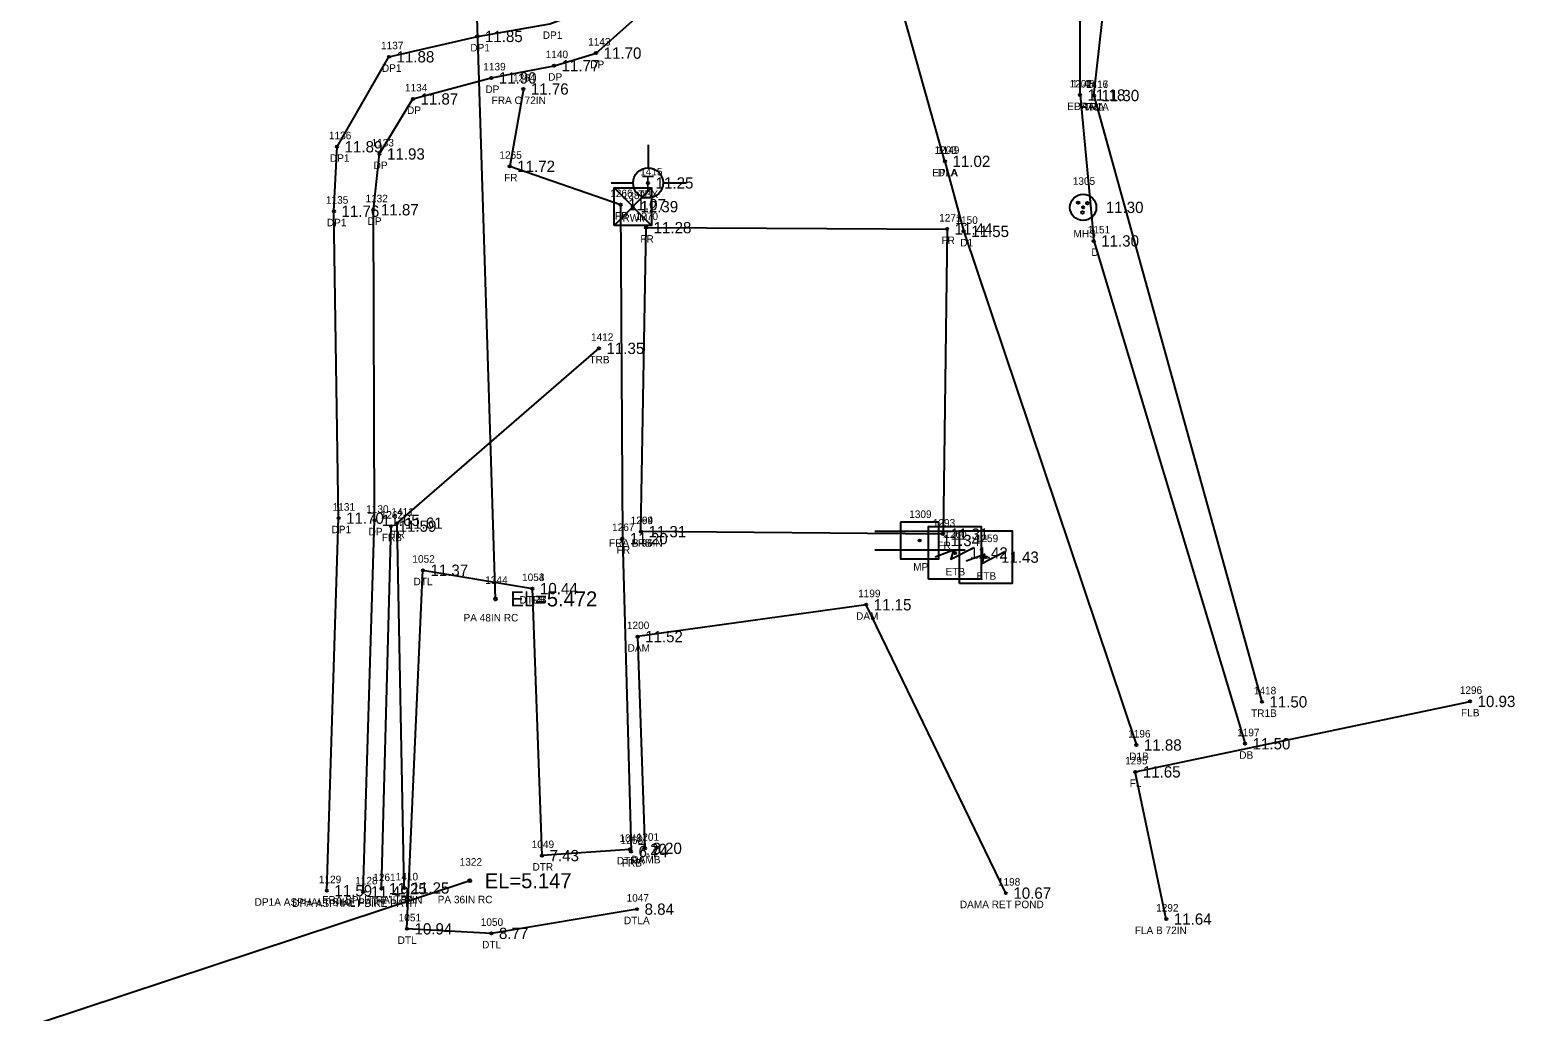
# Model space of a CAD drawing. Extents: x 2072307 to 2072993, y 127574 to 129736.
# Drawn here: x 2072650 to 2072850.3, y 128223.8 to 128354.3 of the extents above; entities that cross this region are included whole.
import ezdxf

# ---------------------------------------------------------------- set-up
doc = ezdxf.new("R2010")
doc.units = 0
for name, color, linetype in [('RD_EX_Dam', 7, 'Continuous'), ('RD_EX_Dam_txCode', 7, 'Continuous'), ('RD_EX_DR_Inlet', 7, 'Continuous'), ('RD_EX_DR_Pipe', 7, 'Continuous'), ('RD_EX_DR_Pipe_txCode', 7, 'Continuous'), ('RD_EX_Driveway', 7, 'Continuous'), ('RD_EX_Driveway_txCode', 7, 'Continuous'), ('RD_EX_Fence_Other', 7, 'Continuous'), ('RD_EX_Fence_Other_txCode', 7, 'Continuous'), ('RD_EX_H2O', 7, 'Continuous'), ('RD_EX_H2O_txCode', 7, 'Continuous'), ('RD_EX_Road', 7, 'Continuous'), ('RD_EX_Road_txCode', 7, 'Continuous'), ('RD_EX_RW', 7, 'Continuous'), ('RD_EX_RW_TxCode', 7, 'Continuous'), ('RD_EX_TX_Dam_ELEV', 7, 'Continuous'), ('RD_EX_TX_Driveway_ELEV', 7, 'Continuous'), ('RD_EX_TX_Fence_Other_ELEV', 7, 'Continuous'), ('RD_EX_TX_H2O_ELEV', 7, 'Continuous'), ('RD_EX_TX_Road_ELEV', 7, 'Continuous'), ('RD_EX_TX_RW_ELEV', 7, 'Continuous'), ('RD_EX_TX_UT_ELEV', 7, 'Continuous'), ('RD_EX_TX_VEG_ELEV', 7, 'Continuous'), ('RD_EX_UT', 7, 'Continuous'), ('RD_EX_UT_txCode', 7, 'Continuous'), ('RD_EX_VEG', 7, 'Continuous'), ('RD_EX_VEG_txCode', 7, 'Continuous'), ('RD_SMD_Locator', 7, 'Continuous'), ('RD_TX_Pipe_ElevEX', 7, 'Continuous')]:
    doc.layers.add(name, color=color, linetype=linetype)

msp = doc.modelspace()

# ---------------------------------------------------------------- linework, layer by layer
at = {"layer": 'RD_EX_Dam'}
msp.add_lwpolyline([(2072779.59, 128239.58), (2072761.03, 128277.92), (2072730.66, 128273.68), (2072731.64, 128245.54)], dxfattribs=at)
at = {"layer": 'RD_EX_DR_Inlet'}
for centre, radius in [((2072789.86, 128330.75), 1.75), ((2072789.2, 128331.38), 0.175), ((2072789.78, 128330.09), 0.175), ((2072790.42, 128331.31), 0.175)]:
    msp.add_circle(centre, radius, dxfattribs=at)
at = {"layer": 'RD_EX_DR_Pipe'}
for p, q in [((2072711.77, 128278.7), (2072708.75, 128375.17)), ((2072708.36, 128241.23), (2072389.02, 128135.57))]:
    msp.add_line(p, q, dxfattribs=at)
at = {"layer": 'RD_EX_Driveway'}
for points in [[(2072689.37, 128239.9), (2072690.93, 128289.43), (2072690.32, 128330.24), (2072690.73, 128338.81), (2072697.63, 128350.77), (2072709.38, 128353.48), (2072719, 128355.15), (2072723.52, 128356.83), (2072727.18, 128360.82), (2072729.07, 128366.04), (2072736.87, 128415.65), (2072743.44, 128446.63), (2072749.73, 128459.37), (2072755.76, 128468.63), (2072761.76, 128476.56), (2072776.61, 128495.01), (2072792.09, 128518.96), (2072805.19, 128542.59), (2072810.66, 128554.44), (2072797.46, 128551.01)], [(2072694.21, 128239.74), (2072695.7, 128289.15), (2072695.56, 128330.43), (2072696.37, 128337.85), (2072700.81, 128345.17), (2072711.22, 128347.96), (2072719.56, 128349.59), (2072725.15, 128351.26), (2072733.07, 128358.33), (2072734.19, 128365.42), (2072741.79, 128414.16), (2072748.82, 128445.27), (2072754.15, 128456.57), (2072759.92, 128465.41), (2072766.21, 128473.75), (2072780.47, 128491.8), (2072796.27, 128516), (2072809.9, 128540.1), (2072821.01, 128555.78)], [(2072789.45, 128345.69), (2072791.26, 128326.29), (2072811.38, 128259.44)], [(2072771.5, 128336.87), (2072773.99, 128327.56), (2072796.93, 128259.27)]]:
    msp.add_lwpolyline(points, dxfattribs=at)
at = {"layer": 'RD_EX_Fence_Other'}
msp.add_line((2072696.63, 128240.18), (2072697.91, 128288.37), dxfattribs=at)
for points in [[(2072715.48, 128346.49), (2072713.67, 128336.21), (2072728.41, 128331.12), (2072728.64, 128286.72), (2072729.79, 128245.11)], [(2072731.1, 128287.64), (2072731.79, 128328.06), (2072771.79, 128327.87), (2072771.24, 128287.31), (2072731.1, 128287.64)], [(2072800.91, 128236.13), (2072796.79, 128255.7), (2072841.27, 128265.07)]]:
    msp.add_lwpolyline(points, dxfattribs=at)
at = {"layer": 'RD_EX_H2O'}
for points in [[(2072730.59, 128237.45), (2072711.24, 128234.23), (2072700.02, 128234.83), (2072702.13, 128282.51), (2072716.69, 128280.07)], [(2072729.65, 128245.4), (2072717.97, 128244.57), (2072716.69, 128280.07)]]:
    msp.add_lwpolyline(points, dxfattribs=at)
at = {"layer": 'RD_EX_Road'}
for points in [[(2072789.45, 128345.69), (2072789.46, 128382.93), (2072788.01, 128408.09), (2072794.06, 128431.26), (2072804.3, 128453.88), (2072840.7, 128525.64), (2072876.68, 128596.08), (2072888.72, 128617.36), (2072893.24, 128622.62), (2072899.84, 128627.36), (2072910.72, 128631.76), (2072918.79, 128632.23), (2072935.82, 128627.02), (2072957.37, 128619.98)], [(2072771.5, 128336.87), (2072760.1, 128377.44)]]:
    msp.add_lwpolyline(points, dxfattribs=at)
at = {"layer": 'RD_EX_RW'}
for p, q in [((2072727.53, 128328.35), (2072732.53, 128333.35)), ((2072732.53, 128328.35), (2072727.53, 128333.35)), ((2072732.53, 128333.35), (2072732.53, 128328.35))]:
    msp.add_line(p, q, dxfattribs=at)
msp.add_lwpolyline([(2072727.53, 128328.35), (2072727.53, 128333.35), (2072732.53, 128333.35), (2072732.53, 128328.35)], close=True, dxfattribs=at)
at = {"layer": 'RD_EX_UT'}
for p, q in [((2072732.06, 128339.07), (2072732.06, 128336)), ((2072727.13, 128334.01), (2072730.06, 128334.01)), ((2072734.06, 128334.01), (2072737.13, 128334.01)), ((2072762.2, 128287.71), (2072774.2, 128287.71)), ((2072762.2, 128285.21), (2072774.2, 128285.21))]:
    msp.add_line(p, q, dxfattribs=at)
for points in [[(2072765.64, 128288.96), (2072770.64, 128288.96), (2072770.64, 128283.96), (2072765.64, 128283.96)], [(2072769.32, 128281.31), (2072769.32, 128288.31), (2072776.32, 128288.31), (2072776.32, 128281.31)], [(2072773.45, 128280.75), (2072773.45, 128287.75), (2072780.45, 128287.75), (2072780.45, 128280.75)]]:
    msp.add_lwpolyline(points, close=True, dxfattribs=at)
for points in [[(2072770.22, 128284.31), (2072772.64, 128285.21), (2072772.29, 128283.96), (2072775.34, 128285.55)], [(2072774.34, 128283.74), (2072776.77, 128284.64), (2072776.42, 128283.39), (2072779.47, 128284.99)]]:
    msp.add_lwpolyline(points, dxfattribs=at)
msp.add_circle((2072732.06, 128334), 2, dxfattribs=at)
at = {"layer": 'RD_EX_VEG'}
msp.add_line((2072791.29, 128345.62), (2072813.61, 128265.01), dxfattribs=at)
for points in [[(2072791.29, 128345.62), (2072800.72, 128429.53), (2072808.9, 128452.58), (2072870.32, 128568.64), (2072876.57, 128573.6), (2072916.77, 128564.68), (2072920.97, 128548.67)], [(2072699.63, 128240.27), (2072698.73, 128288.77), (2072725.53, 128312.01)]]:
    msp.add_lwpolyline(points, dxfattribs=at)
at = {"layer": 'RD_SMD_Locator'}
for centre, radius in [((2072709.38, 128353.48), 0.15), ((2072697.63, 128350.77), 0.15), ((2072719.56, 128349.59), 0.15), ((2072725.15, 128351.26), 0.15), ((2072711.22, 128347.96), 0.15), ((2072715.48, 128346.49), 0.15), ((2072789.45, 128345.69), 0.15), ((2072789.45, 128345.69), 0.15), ((2072791.29, 128345.62), 0.15), ((2072791.29, 128345.62), 0.15), ((2072700.81, 128345.17), 0.15), ((2072690.73, 128338.81), 0.15), ((2072696.37, 128337.85), 0.15), ((2072713.67, 128336.21), 0.15), ((2072771.5, 128336.87), 0.15), ((2072771.5, 128336.87), 0.15), ((2072732.06, 128334), 0.15), ((2072690.32, 128330.24), 0.15), ((2072695.56, 128330.43), 0.15), ((2072728.41, 128331.12), 0.15), ((2072730.03, 128330.85), 0.15), ((2072789.86, 128330.75), 0.15), ((2072731.79, 128328.06), 0.15), ((2072771.79, 128327.87), 0.15), ((2072773.99, 128327.56), 0.15), ((2072791.26, 128326.29), 0.15), ((2072725.53, 128312.01), 0.15), ((2072690.93, 128289.43), 0.15), ((2072695.7, 128289.15), 0.15), ((2072697.91, 128288.37), 0.15), ((2072698.73, 128288.77), 0.15), ((2072731.1, 128287.64), 0.15), ((2072731.1, 128287.64), 0.15), ((2072728.64, 128286.72), 0.15), ((2072768.14, 128286.46), 0.15), ((2072771.24, 128287.31), 0.15), ((2072772.82, 128284.81), 0.15), ((2072776.95, 128284.25), 0.15), ((2072702.13, 128282.51), 0.15), ((2072716.69, 128280.07), 0.15), ((2072716.69, 128280.07), 0.15), ((2072711.77, 128278.7), 0.2), ((2072761.03, 128277.92), 0.15), ((2072730.66, 128273.68), 0.15), ((2072813.61, 128265.01), 0.15), ((2072841.27, 128265.07), 0.15), ((2072811.38, 128259.44), 0.15), ((2072796.93, 128259.27), 0.15), ((2072796.79, 128255.7), 0.15), ((2072729.65, 128245.4), 0.15), ((2072731.64, 128245.54), 0.15), ((2072717.97, 128244.57), 0.15), ((2072729.79, 128245.11), 0.15), ((2072689.37, 128239.9), 0.15), ((2072694.21, 128239.74), 0.15), ((2072696.63, 128240.18), 0.15), ((2072699.63, 128240.27), 0.15), ((2072708.36, 128241.23), 0.2), ((2072779.59, 128239.58), 0.15), ((2072730.59, 128237.45), 0.15), ((2072800.91, 128236.13), 0.15), ((2072700.02, 128234.83), 0.15), ((2072711.24, 128234.23), 0.15)]:
    msp.add_circle(centre, radius, dxfattribs=at)

# ---------------------------------------------------------------- texts
at = {"layer": 'RD_EX_Dam_txCode'}
for s, p in [('1199', (2072759.96, 128278.92)), ('1200', (2072729.24, 128274.68)), ('DAM', (2072759.69, 128275.92)), ('DAM', (2072729.33, 128271.68)), ('1201', (2072730.54, 128246.54)), ('DAMB', (2072729.84, 128243.54)), ('1198', (2072778.53, 128240.58)), ('DAMA RET POND', (2072773.48, 128237.58))]:
    msp.add_text(s, height=1, dxfattribs=at).set_placement(p)
at = {"layer": 'RD_EX_DR_Pipe_txCode'}
for s, p in [('1344', (2072710.42, 128280.7)), ('PA 48IN RC', (2072707.53, 128275.7)), ('1322', (2072707.02, 128243.23)), ('PA 36IN RC', (2072704.1, 128238.23))]:
    msp.add_text(s, height=1, dxfattribs=at).set_placement(p)
at = {"layer": 'RD_EX_Driveway_txCode'}
for s, p in [('DP1', (2072718.06, 128353.15)), ('1137', (2072696.57, 128351.77)), ('DP1', (2072708.44, 128351.48)), ('1143', (2072724.09, 128352.26)), ('DP1', (2072696.69, 128348.77)), ('1139', (2072710.16, 128348.96)), ('1140', (2072718.45, 128350.59)), ('DP', (2072724.37, 128349.26)), ('DP', (2072718.78, 128347.59)), ('1148', (2072788.38, 128346.69)), ('1134', (2072699.75, 128346.17)), ('DP', (2072710.44, 128345.96)), ('DP', (2072700.03, 128343.17)), ('DA', (2072788.65, 128343.69)), ('1136', (2072689.65, 128339.81)), ('1133', (2072695.31, 128338.85)), ('DP1', (2072689.79, 128336.81)), ('1149', (2072770.44, 128337.87)), ('DP', (2072695.59, 128335.85)), ('D1A', (2072770.54, 128334.87)), ('1135', (2072689.25, 128331.24)), ('1132', (2072694.5, 128331.43)), ('DP1', (2072689.37, 128328.24)), ('DP', (2072694.78, 128328.43)), ('1150', (2072772.89, 128328.56)), ('1151', (2072790.48, 128327.29)), ('D1', (2072773.52, 128325.56)), ('D', (2072790.95, 128324.29)), ('1131', (2072690.15, 128290.43)), ('1130', (2072694.6, 128290.15)), ('DP1', (2072689.99, 128287.43)), ('DP', (2072694.92, 128287.15)), ('1196', (2072795.84, 128260.27)), ('1197', (2072810.32, 128260.44)), ('D1B', (2072795.98, 128257.27)), ('DB', (2072810.6, 128257.44)), ('1129', (2072688.31, 128240.9)), ('1128', (2072693.14, 128240.74)), ('DP1A ASPHALT BIKE PATH', (2072679.78, 128237.9)), ('DPA ASPHALT BIKE PATH', (2072684.77, 128237.74))]:
    msp.add_text(s, height=1, dxfattribs=at).set_placement(p)
at = {"layer": 'RD_EX_Fence_Other_txCode'}
for s, p in [('1264', (2072714.11, 128347.49)), ('FRA C 72IN', (2072711.27, 128344.49)), ('1265', (2072712.3, 128337.21)), ('FR', (2072712.92, 128334.21)), ('1266', (2072727.02, 128332.12)), ('FR', (2072727.66, 128329.12)), ('1270', (2072730.4, 128329.06)), ('1271', (2072770.73, 128328.87)), ('FR', (2072731.03, 128326.06)), ('FR', (2072771.04, 128325.87)), ('1262', (2072696.54, 128289.37)), ('1269', (2072729.73, 128288.64)), ('1294', (2072729.75, 128288.64)), ('1267', (2072727.27, 128287.72)), ('1293', (2072769.89, 128288.31)), ('FRB', (2072696.68, 128286.37)), ('FRA B 96IN', (2072726.86, 128285.64)), ('FR', (2072727.88, 128284.72)), ('FRB', (2072729.87, 128285.64)), ('FR', (2072770.49, 128285.31)), ('1296', (2072839.9, 128266.07)), ('FLB', (2072840.07, 128263.07)), ('1295', (2072795.44, 128256.7)), ('FL', (2072796.05, 128253.7)), ('1268', (2072728.42, 128246.11)), ('FRB', (2072728.57, 128243.11)), ('1261', (2072695.54, 128241.18)), ('FRA SPLIT RAIL 30IN', (2072688.76, 128238.18)), ('1292', (2072799.56, 128237.13)), ('FLA B 72IN', (2072796.72, 128234.13))]:
    msp.add_text(s, height=1, dxfattribs=at).set_placement(p)
at = {"layer": 'RD_EX_H2O_txCode'}
for s, p in [('1052', (2072700.74, 128283.51)), ('1053', (2072715.31, 128281.07)), ('1054', (2072715.31, 128281.07)), ('DTL', (2072700.89, 128280.51)), ('DTRB', (2072714.95, 128278.07)), ('DTLB', (2072714.97, 128278.07)), ('1049', (2072716.59, 128245.57)), ('1048', (2072728.26, 128246.4)), ('DTR', (2072716.7, 128242.57)), ('DTRA', (2072727.89, 128243.4)), ('1047', (2072729.2, 128238.45)), ('1051', (2072698.92, 128235.83)), ('1050', (2072709.82, 128235.23)), ('DTLA', (2072728.85, 128235.45)), ('DTL', (2072698.78, 128232.83)), ('DTL', (2072710, 128232.23))]:
    msp.add_text(s, height=1, dxfattribs=at).set_placement(p)
at = {"layer": 'RD_EX_Road_txCode'}
for s, p in [('1202', (2072788.06, 128346.69)), ('EPRA', (2072787.73, 128343.69)), ('1203', (2072770.11, 128337.87)), ('EPLA', (2072769.81, 128334.87))]:
    msp.add_text(s, height=1, dxfattribs=at).set_placement(p)
at = {"layer": 'RD_EX_RW_TxCode'}
for s, p in [('1382', (2072728.68, 128331.85)), ('RWM', (2072728.65, 128328.85))]:
    msp.add_text(s, height=1, dxfattribs=at).set_placement(p)
at = {"layer": 'RD_EX_TX_Dam_ELEV'}
for s, p in [('11.15', (2072762.03, 128277.17)), ('11.52', (2072731.66, 128272.93)), ('8.20', (2072732.64, 128244.79)), ('10.67', (2072780.59, 128238.83))]:
    msp.add_text(s, height=1.5, dxfattribs=at).set_placement(p)
at = {"layer": 'RD_EX_TX_Driveway_ELEV'}
for s, p in [('11.85', (2072710.38, 128352.73)), ('11.70', (2072726.15, 128350.51)), ('11.88', (2072698.63, 128350.02)), ('11.77', (2072720.56, 128348.84)), ('11.90', (2072712.22, 128347.21)), ('11.87', (2072701.81, 128344.42)), ('11.18', (2072790.45, 128344.94)), ('11.89', (2072691.73, 128338.06)), ('11.93', (2072697.37, 128337.1)), ('11.02', (2072772.5, 128336.12)), ('11.76', (2072691.32, 128329.49)), ('11.87', (2072696.56, 128329.68)), ('11.55', (2072774.99, 128326.81)), ('11.30', (2072792.26, 128325.54)), ('11.70', (2072691.93, 128288.68)), ('11.65', (2072696.7, 128288.4)), ('11.88', (2072797.93, 128258.52)), ('11.50', (2072812.38, 128258.69)), ('11.59', (2072690.37, 128239.15)), ('11.49', (2072695.21, 128238.99))]:
    msp.add_text(s, height=1.5, dxfattribs=at).set_placement(p)
at = {"layer": 'RD_EX_TX_Fence_Other_ELEV'}
for s, p in [('11.76', (2072716.48, 128345.74)), ('11.72', (2072714.67, 128335.46)), ('11.07', (2072729.41, 128330.37)), ('11.28', (2072732.79, 128327.31)), ('11.44', (2072772.79, 128327.12)), ('11.59', (2072698.91, 128287.62)), ('11.31', (2072732.1, 128286.89)), ('11.31', (2072732.1, 128286.89)), ('11.31', (2072772.24, 128286.56)), ('11.20', (2072729.64, 128285.97)), ('10.93', (2072842.27, 128264.32)), ('11.65', (2072797.79, 128254.95)), ('6.74', (2072730.79, 128244.36)), ('11.25', (2072697.63, 128239.43)), ('11.64', (2072801.91, 128235.38))]:
    msp.add_text(s, height=1.5, dxfattribs=at).set_placement(p)
at = {"layer": 'RD_EX_TX_H2O_ELEV'}
for s, p in [('11.37', (2072703.13, 128281.76)), ('10.44', (2072717.69, 128279.32)), ('10.44', (2072717.69, 128279.32)), ('7.20', (2072730.65, 128244.65)), ('7.43', (2072718.97, 128243.82)), ('8.84', (2072731.59, 128236.7)), ('10.94', (2072701.02, 128234.08)), ('8.77', (2072712.24, 128233.48))]:
    msp.add_text(s, height=1.5, dxfattribs=at).set_placement(p)
at = {"layer": 'RD_EX_TX_Road_ELEV'}
for s, p in [('11.18', (2072790.45, 128344.94)), ('11.02', (2072772.5, 128336.12))]:
    msp.add_text(s, height=1.5, dxfattribs=at).set_placement(p)
at = {"layer": 'RD_EX_TX_RW_ELEV'}
msp.add_text('12.39', height=1.5, dxfattribs=at).set_placement((2072731.03, 128330.1))
at = {"layer": 'RD_EX_TX_UT_ELEV'}
for s, p in [('11.25', (2072733.06, 128333.25)), ('11.30', (2072792.86, 128330)), ('11.34', (2072771.14, 128285.71)), ('11.42', (2072774.82, 128284.06)), ('11.43', (2072778.95, 128283.5))]:
    msp.add_text(s, height=1.5, dxfattribs=at).set_placement(p)
at = {"layer": 'RD_EX_TX_VEG_ELEV'}
for s, p in [('11.30', (2072792.29, 128344.87)), ('11.30', (2072792.29, 128344.87)), ('11.35', (2072726.53, 128311.26)), ('11.61', (2072699.73, 128288.02)), ('11.50', (2072814.61, 128264.26)), ('11.25', (2072700.63, 128239.52))]:
    msp.add_text(s, height=1.5, dxfattribs=at).set_placement(p)
at = {"layer": 'RD_EX_UT'}
msp.add_text('T', height=2, dxfattribs=at).set_placement((2072731.21, 128332.95))
at = {"layer": 'RD_EX_UT_txCode'}
for s, p in [('1415', (2072731, 128335)), ('1305', (2072788.48, 128333.75)), ('TBX', (2072730.78, 128332)), ('MHS', (2072788.57, 128326.75)), ('1309', (2072766.75, 128289.46)), ('1260', (2072771.41, 128286.81)), ('1259', (2072775.6, 128286.25)), ('MP', (2072767.29, 128282.46)), ('ETB', (2072771.58, 128281.81)), ('ETB', (2072775.7, 128281.25))]:
    msp.add_text(s, height=1, dxfattribs=at).set_placement(p)
at = {"layer": 'RD_EX_VEG_txCode'}
for s, p in [('1416', (2072790.21, 128346.62)), ('1417', (2072790.23, 128346.62)), ('TR1A', (2072789.85, 128343.62)), ('TRA', (2072790.01, 128343.62)), ('1412', (2072724.47, 128313.01)), ('TRB', (2072724.26, 128310.01)), ('1411', (2072697.95, 128289.77)), ('TR', (2072697.93, 128286.77)), ('1418', (2072812.54, 128266.01)), ('TR1B', (2072812.17, 128263.01)), ('1410', (2072698.52, 128241.27)), ('TRA', (2072698.34, 128238.27))]:
    msp.add_text(s, height=1, dxfattribs=at).set_placement(p)
at = {"layer": 'RD_TX_Pipe_ElevEX'}
for s, p in [('EL=5.472', (2072713.77, 128277.7)), ('EL=5.147', (2072710.36, 128240.23))]:
    msp.add_text(s, height=2, dxfattribs=at).set_placement(p)

doc.saveas('drawing.dxf')
